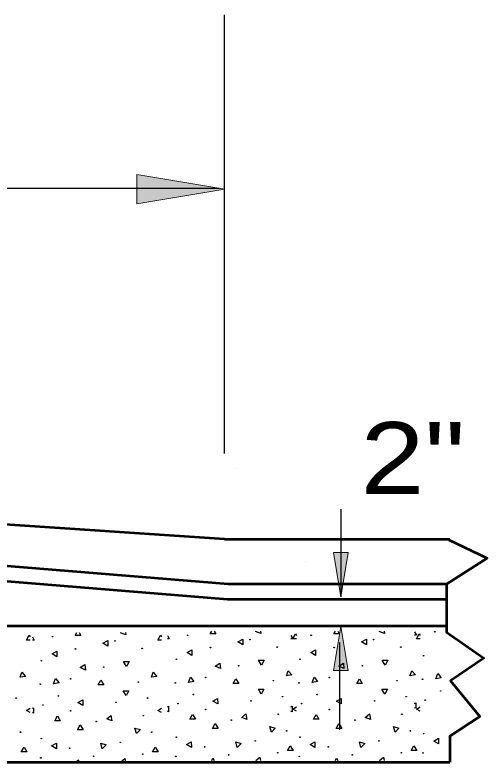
# Model space of a CAD drawing. Extents: x 75.6 to 110.9, y 28 to 50.
# Drawn here: x 97.036 to 98.023, y 39.251 to 40.813 of the extents above; entities that cross this region are included whole.
import ezdxf
from ezdxf.enums import TextEntityAlignment as Align

# ---------------------------------------------------------------- set-up
doc = ezdxf.new("R2010")
doc.units = 0
doc.header["$LTSCALE"] = 0.06
doc.layers.add('1', color=7, linetype='Continuous', lineweight=25)
doc.layers.add('3', color=7, linetype='Continuous', lineweight=13)

msp = doc.modelspace()

# ---------------------------------------------------------------- hatches: boundary and pattern name
at = {"layer": '3'}
for points in [[(97.29017, 40.4795), (97.29017, 40.418), (97.47475, 40.44875), (97.47475, 40.44875)], [(97.70142, 39.68892), (97.73217, 39.68892), (97.71675, 39.59658), (97.71675, 39.59658)], [(97.70142, 39.44217), (97.73217, 39.44217), (97.71675, 39.5345), (97.71675, 39.5345)], [(97.70142, 39.44217), (97.73217, 39.44217), (97.71675, 39.5345), (97.71675, 39.5345)]]:
    msp.add_hatch(color=256, dxfattribs=at).paths.add_polyline_path(points)

# ---------------------------------------------------------------- linework, layer by layer
at = {"layer": '1'}
for p, q in [((97.47392, 39.896), (97.47392, 40.81275)), ((97.46283, 40.45008), (94.47375, 40.45008)), ((97.1615, 39.51575), (97.16483, 39.5215)), ((97.16983, 39.5215), (97.17317, 39.51575)), ((97.25658, 39.521), (97.25733, 39.5215)), ((97.26758, 39.517), (97.25658, 39.521)), ((97.26683, 39.5215), (97.26758, 39.517)), ((97.44383, 39.51867), (97.44717, 39.52433)), ((97.45542, 39.51867), (97.44383, 39.51867)), ((97.45208, 39.52433), (97.45542, 39.51867)), ((97.53892, 39.52383), (97.53958, 39.52433)), ((97.54992, 39.51983), (97.53892, 39.52383)), ((97.54908, 39.52433), (97.54992, 39.51983)), ((97.61658, 39.50875), (97.62242, 39.51883)), ((97.62242, 39.51883), (97.62433, 39.51558)), ((97.70225, 39.51867), (97.70558, 39.52433)), ((97.71392, 39.51867), (97.70225, 39.51867)), ((97.71058, 39.52433), (97.71392, 39.51867)), ((97.79742, 39.52383), (97.79817, 39.52433)), ((97.80842, 39.51983), (97.79742, 39.52383)), ((97.80758, 39.52433), (97.80842, 39.51983)), ((97.87142, 39.523), (97.87533, 39.51617)), ((97.87517, 39.50875), (97.88092, 39.51883)), ((97.88092, 39.51883), (97.88283, 39.51558)), ((97.05983, 39.50592), (97.06558, 39.516)), ((97.0675, 39.50592), (97.05983, 39.50592)), ((97.06558, 39.516), (97.0675, 39.51267)), ((97.072, 39.51267), (97.076, 39.50592)), ((97.076, 39.50592), (97.072, 39.50592)), ((97.17317, 39.51575), (97.1615, 39.51575)), ((97.33433, 39.50592), (97.34017, 39.516)), ((97.342, 39.50592), (97.33433, 39.50592)), ((97.34017, 39.516), (97.342, 39.51267)), ((97.35433, 39.51558), (97.35825, 39.50875)), ((97.35825, 39.50875), (97.35433, 39.50875)), ((97.61283, 39.51558), (97.61683, 39.50875)), ((97.61683, 39.50875), (97.61283, 39.50875)), ((97.62433, 39.50875), (97.61658, 39.50875)), ((97.87533, 39.51617), (97.87142, 39.51617)), ((97.88283, 39.50875), (97.87517, 39.50875)), ((97.072, 39.36317), (97.07433, 39.3645)), ((97.072, 39.36317), (97.07433, 39.3645)), ((97.07433, 39.3645), (97.07442, 39.35283)), ((97.07433, 39.3645), (97.07442, 39.35283)), ((97.35433, 39.366), (97.35658, 39.36733)), ((97.35433, 39.366), (97.35658, 39.36733)), ((97.35658, 39.36733), (97.35667, 39.35575)), ((97.35658, 39.36733), (97.35667, 39.35575)), ((97.61283, 39.366), (97.61517, 39.36733)), ((97.61283, 39.366), (97.61517, 39.36733)), ((97.61517, 39.36733), (97.61525, 39.35575)), ((97.61517, 39.36733), (97.61525, 39.35575)), ((97.87142, 39.37342), (97.87367, 39.37475)), ((97.87142, 39.37342), (97.87367, 39.37475)), ((97.87375, 39.36317), (97.87142, 39.3645)), ((97.87375, 39.36317), (97.87142, 39.3645)), ((97.87367, 39.37475), (97.87375, 39.36317)), ((97.87367, 39.37475), (97.87375, 39.36317)), ((97.07442, 39.35283), (97.072, 39.35417)), ((97.07442, 39.35283), (97.072, 39.35417)), ((97.35667, 39.35575), (97.35433, 39.35708)), ((97.35667, 39.35575), (97.35433, 39.35708)), ((97.61525, 39.35575), (97.61283, 39.35708)), ((97.61525, 39.35575), (97.61283, 39.35708)), ((97.94517, 39.25083), (97.94517, 39.30508))]:
    msp.add_line(p, q, dxfattribs=at)
at = {"layer": '1', "lineweight": 53}
for p, q in [((97.47392, 39.71692), (94.47375, 39.91475)), ((94.47375, 39.87142), (97.48125, 39.62317)), ((94.47108, 39.8355), (97.48017, 39.59133)), ((97.47392, 39.71692), (97.94517, 39.71692)), ((97.48125, 39.62317), (97.938, 39.62317)), ((97.48017, 39.59133), (97.938, 39.59133)), ((97.938, 39.53517), (93.85133, 39.53517)), ((93.85133, 39.25083), (97.94517, 39.25083))]:
    msp.add_line(p, q, dxfattribs=at)
msp.add_lwpolyline([(97.94308, 39.71567), (98.02283, 39.67683), (97.938, 39.6225), (97.938, 39.52233), (98.01608, 39.46808), (97.9465, 39.4205), (98.00767, 39.34583), (97.94517, 39.30508), (97.94517, 39.25083)], dxfattribs=at)
at = {"layer": '1'}
for points in [[(97.22958, 39.49333), (97.21958, 39.49917), (97.22958, 39.505)], [(97.51192, 39.49617), (97.50183, 39.502), (97.51192, 39.50792)], [(97.77042, 39.49617), (97.76033, 39.502), (97.77042, 39.50792)], [(97.40558, 39.47392), (97.3955, 39.47975), (97.4055, 39.48558)], [(97.66408, 39.47392), (97.654, 39.47975), (97.664, 39.48558)], [(97.12325, 39.471), (97.11325, 39.47683), (97.12325, 39.48267)], [(97.18292, 39.44325), (97.17233, 39.44817), (97.18183, 39.45475)], [(97.26858, 39.45075), (97.26275, 39.46092), (97.27442, 39.46092)], [(97.46525, 39.44617), (97.45458, 39.451), (97.46417, 39.45767)], [(97.55092, 39.45367), (97.545, 39.46375), (97.55667, 39.46375)], [(97.72367, 39.44617), (97.71317, 39.451), (97.72258, 39.45767)], [(97.80942, 39.45367), (97.80358, 39.46375), (97.81525, 39.46375)], [(97.05783, 39.43), (97.04633, 39.428), (97.05025, 39.43892)], [(97.33233, 39.43), (97.32092, 39.428), (97.32483, 39.43892)], [(97.61458, 39.43292), (97.60325, 39.43092), (97.60717, 39.44175)], [(97.87317, 39.43292), (97.86167, 39.43092), (97.86558, 39.44175)], [(97.12775, 39.41658), (97.11625, 39.41458), (97.12025, 39.42558)], [(97.41, 39.4195), (97.39858, 39.4175), (97.40258, 39.42842)], [(97.5035, 39.41483), (97.49183, 39.41483), (97.49758, 39.42492)], [(97.66858, 39.4195), (97.65708, 39.4175), (97.661, 39.42842)], [(97.762, 39.41483), (97.75033, 39.41483), (97.75617, 39.42492)], [(97.92708, 39.42692), (97.91558, 39.42492), (97.91958, 39.43583)], [(97.22125, 39.412), (97.20958, 39.412), (97.21533, 39.422)], [(97.26817, 39.39), (97.26225, 39.4), (97.27392, 39.4)], [(97.55042, 39.39283), (97.54458, 39.403), (97.55625, 39.403)], [(97.80892, 39.39283), (97.80308, 39.403), (97.81475, 39.403)], [(97.17725, 39.36933), (97.16717, 39.37525), (97.17725, 39.381)], [(97.45958, 39.37233), (97.44942, 39.37817), (97.4595, 39.384)], [(97.718, 39.37233), (97.70792, 39.37817), (97.718, 39.384)], [(97.1305, 39.33733), (97.11883, 39.33733), (97.12458, 39.34733)], [(97.23842, 39.337), (97.22742, 39.341), (97.23633, 39.3485)], [(97.41283, 39.34025), (97.40117, 39.34025), (97.40692, 39.35033)], [(97.52067, 39.34), (97.50975, 39.344), (97.51858, 39.35133)], [(97.67125, 39.34025), (97.65958, 39.34025), (97.66542, 39.35033)], [(97.77925, 39.34), (97.76825, 39.344), (97.77717, 39.35133)], [(97.46025, 39.32133), (97.44858, 39.32133), (97.45442, 39.33133)], [(97.71883, 39.32133), (97.70717, 39.32133), (97.71292, 39.33133)], [(97.178, 39.31842), (97.16633, 39.31842), (97.17217, 39.3285)], [(97.28958, 39.31067), (97.28658, 39.322), (97.29783, 39.319)], [(97.57183, 39.31358), (97.56883, 39.32483), (97.58008, 39.32183)], [(97.83033, 39.31358), (97.82733, 39.32483), (97.83858, 39.32183)], [(97.92158, 39.289), (97.91142, 39.29475), (97.9215, 39.30067)], [(97.12225, 39.27867), (97.11208, 39.2845), (97.12217, 39.29033)], [(97.21825, 39.27867), (97.21525, 39.29), (97.22642, 39.287)], [(97.4045, 39.28158), (97.39442, 39.28733), (97.40442, 39.29325)], [(97.5005, 39.28158), (97.4975, 39.29283), (97.50875, 39.28983)], [(97.61725, 39.27475), (97.60558, 39.27475), (97.61142, 39.28483)], [(97.663, 39.28158), (97.65292, 39.28733), (97.66292, 39.29325)], [(97.759, 39.28158), (97.756, 39.29283), (97.76725, 39.28983)], [(97.87575, 39.27475), (97.86408, 39.27475), (97.86992, 39.28483)], [(97.06042, 39.27192), (97.04875, 39.27192), (97.05458, 39.282)], [(97.33492, 39.27192), (97.32325, 39.27192), (97.32908, 39.282)]]:
    msp.add_lwpolyline(points, close=True, dxfattribs=at)
for points in [[(97.0675, 39.35417), (97.05975, 39.35867), (97.0675, 39.36317)], [(97.342, 39.35417), (97.33425, 39.35867), (97.342, 39.36317)], [(97.62433, 39.35708), (97.61658, 39.36158), (97.62433, 39.366)], [(97.88283, 39.35708), (97.87508, 39.36158), (97.88283, 39.366)], [(97.16483, 39.2515), (97.16725, 39.25575), (97.16983, 39.2515)], [(97.25733, 39.2515), (97.26558, 39.25833), (97.26683, 39.2515)], [(97.25733, 39.2515), (97.26558, 39.25833), (97.26683, 39.2515)], [(97.44717, 39.25433), (97.44958, 39.25867), (97.45208, 39.25433)], [(97.53958, 39.25433), (97.54783, 39.26133), (97.54908, 39.25433)], [(97.53958, 39.25433), (97.54783, 39.26133), (97.54908, 39.25433)], [(97.70558, 39.25433), (97.70808, 39.25867), (97.71058, 39.25433)], [(97.79817, 39.25433), (97.80633, 39.26133), (97.80758, 39.25433)], [(97.79817, 39.25433), (97.80633, 39.26133), (97.80758, 39.25433)]]:
    msp.add_lwpolyline(points, dxfattribs=at)
for centre in [(97.91359, 39.52323), (97.11424, 39.51293), (97.24476, 39.504), (97.39654, 39.51583), (97.52706, 39.5069), (97.65504, 39.51583), (97.78556, 39.5069), (97.16221, 39.48728), (97.30166, 39.48839), (97.44451, 39.49018), (97.58396, 39.49129), (97.70301, 39.49018), (97.84246, 39.49129), (97.89014, 39.47304), (97.09079, 39.46274), (97.37309, 39.46564), (97.63159, 39.46564), (97.22134, 39.44935), (97.50364, 39.45225), (97.76214, 39.45225), (97.15215, 39.4248), (97.43445, 39.4277), (97.69295, 39.4277), (97.88791, 39.42394), (97.08857, 39.41364), (97.29383, 39.4181), (97.37087, 39.41654), (97.57613, 39.421), (97.62937, 39.41654), (97.83463, 39.421), (97.4088, 39.39199), (97.6673, 39.39199), (97.92585, 39.39939), (97.03825, 39.38464), (97.1265, 39.38909), (97.24699, 39.37571), (97.3128, 39.38464), (97.52929, 39.37861), (97.5951, 39.38754), (97.78779, 39.37861), (97.8536, 39.38754), (97.89349, 39.38043), (97.09414, 39.37013), (97.37645, 39.37303), (97.43445, 39.36076), (97.63495, 39.37303), (97.69295, 39.36076), (97.15215, 39.35786), (97.30389, 39.34783), (97.58619, 39.35073), (97.84469, 39.35073), (97.2057, 39.33554), (97.488, 39.33844), (97.7465, 39.33844), (97.04718, 39.31325), (97.32173, 39.31325), (97.60403, 39.31615), (97.86253, 39.31615), (97.09079, 39.29986), (97.37309, 39.30276), (97.63159, 39.30276), (97.89014, 39.31016), (97.25592, 39.29203), (97.43222, 39.28267), (97.53822, 39.29493), (97.69072, 39.28267), (97.79672, 39.29493), (97.14992, 39.27977), (97.30277, 39.2675), (97.58507, 39.2704), (97.84356, 39.2704), (97.88904, 39.27), (97.08969, 39.2597), (97.20012, 39.26303), (97.37199, 39.2626), (97.48242, 39.26593), (97.63049, 39.2626), (97.74092, 39.26593)]:
    msp.add_circle(centre, 0.000647, dxfattribs=at)
at = {"layer": '3'}
for p, q in [((97.49608, 39.865), (97.496, 39.865)), ((97.64375, 39.66925), (97.64367, 39.66925))]:
    msp.add_line(p, q, dxfattribs=at)
at = {"layer": '3', "lineweight": 25}
for p, q in [((97.71675, 39.77933), (97.71675, 39.59658)), ((97.715, 39.31817), (97.715, 39.501))]:
    msp.add_line(p, q, dxfattribs=at)
at = {"layer": '3'}
for points in [[(97.29017, 40.4795), (97.29017, 40.418), (97.47475, 40.44875), (97.47475, 40.44875)], [(97.70142, 39.68892), (97.73217, 39.68892), (97.71675, 39.59658), (97.71675, 39.59658)], [(97.70142, 39.44217), (97.73217, 39.44217), (97.71675, 39.5345), (97.71675, 39.5345)], [(97.70142, 39.44217), (97.73217, 39.44217), (97.71675, 39.5345), (97.71675, 39.5345)]]:
    msp.add_lwpolyline(points, close=True, dxfattribs=at)

# ---------------------------------------------------------------- texts
at = {"layer": '1', "width": 1.2}
msp.add_text('2"', height=0.15, dxfattribs=at).set_placement((97.86775, 39.81158), align=Align.CENTER)

doc.saveas('drawing.dxf')
